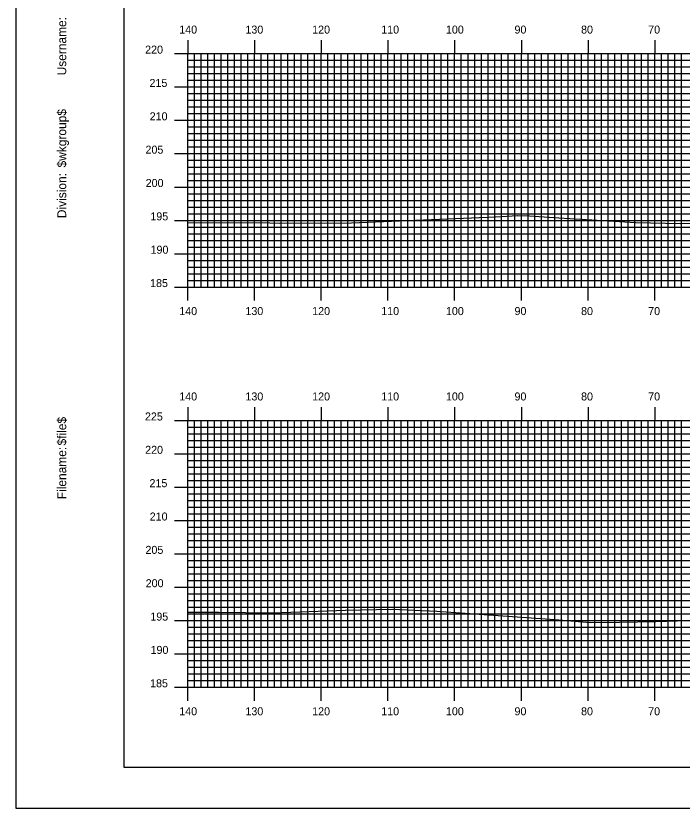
# Model space of a CAD drawing. Extents: x 1812554 to 1812897, y 442591 to 442811.
# Drawn here: x 1812554.2 to 1812654, y 442590.5 to 442709.3 of the extents above; entities that cross this region are included whole.
import ezdxf

# ---------------------------------------------------------------- set-up
doc = ezdxf.new("R2010")
doc.units = 0
for name, color, linetype in [('BORDER', 7, 'Continuous'), ('H_V ANNOTATION', 7, 'Continuous'), ('MAJOR', 7, 'Continuous'), ('MINOR', 7, 'Continuous'), ('PLOT BOUNDARY', 7, 'Continuous'), ('S_Roadway_Centerline', 7, 'Continuous')]:
    doc.layers.add(name, color=color, linetype=linetype)

msp = doc.modelspace()

# ---------------------------------------------------------------- linework, layer by layer
at = {"layer": 'BORDER'}
msp.add_lwpolyline([(1812570.34, 442596.67), (1812890.34, 442596.67), (1812890.34, 442806.67), (1812570.34, 442806.67)], close=True, dxfattribs=at)
at = {"layer": 'MAJOR'}
for p, q in [((1812579.94, 442705.67), (1812579.94, 442703.67)), ((1812589.94, 442705.67), (1812589.94, 442703.67)), ((1812599.94, 442705.67), (1812599.94, 442703.67)), ((1812609.94, 442705.67), (1812609.94, 442703.67)), ((1812619.94, 442705.67), (1812619.94, 442703.67)), ((1812629.94, 442705.67), (1812629.94, 442703.67)), ((1812639.94, 442705.67), (1812639.94, 442703.67)), ((1812649.94, 442705.67), (1812649.94, 442703.67)), ((1812577.94, 442703.67), (1812579.94, 442703.67)), ((1812579.94, 442703.67), (1812859.94, 442703.67)), ((1812579.94, 442668.67), (1812579.94, 442703.67)), ((1812579.94, 442668.67), (1812579.94, 442703.67)), ((1812579.94, 442703.67), (1812859.94, 442703.67)), ((1812589.94, 442668.67), (1812589.94, 442703.67)), ((1812599.94, 442668.67), (1812599.94, 442703.67)), ((1812609.94, 442668.67), (1812609.94, 442703.67)), ((1812619.94, 442668.67), (1812619.94, 442703.67)), ((1812629.94, 442668.67), (1812629.94, 442703.67)), ((1812639.94, 442668.67), (1812639.94, 442703.67)), ((1812649.94, 442668.67), (1812649.94, 442703.67)), ((1812577.94, 442698.67), (1812579.94, 442698.67)), ((1812579.94, 442698.67), (1812859.94, 442698.67)), ((1812577.94, 442693.67), (1812579.94, 442693.67)), ((1812579.94, 442693.67), (1812859.94, 442693.67)), ((1812577.94, 442688.67), (1812579.94, 442688.67)), ((1812579.94, 442688.67), (1812859.94, 442688.67)), ((1812577.94, 442683.67), (1812579.94, 442683.67)), ((1812579.94, 442683.67), (1812859.94, 442683.67)), ((1812577.94, 442678.67), (1812579.94, 442678.67)), ((1812579.94, 442678.67), (1812859.94, 442678.67)), ((1812577.94, 442673.67), (1812579.94, 442673.67)), ((1812579.94, 442673.67), (1812859.94, 442673.67)), ((1812577.94, 442668.67), (1812579.94, 442668.67)), ((1812579.94, 442668.67), (1812859.94, 442668.67)), ((1812579.94, 442668.67), (1812859.94, 442668.67)), ((1812579.94, 442666.66), (1812579.94, 442668.67)), ((1812589.94, 442666.66), (1812589.94, 442668.67)), ((1812599.94, 442666.66), (1812599.94, 442668.67)), ((1812609.94, 442666.66), (1812609.94, 442668.67)), ((1812619.94, 442666.66), (1812619.94, 442668.67)), ((1812629.94, 442666.66), (1812629.94, 442668.67)), ((1812639.94, 442666.66), (1812639.94, 442668.67)), ((1812649.94, 442666.66), (1812649.94, 442668.67)), ((1812579.94, 442650.67), (1812579.94, 442648.67)), ((1812589.94, 442650.67), (1812589.94, 442648.67)), ((1812599.94, 442650.67), (1812599.94, 442648.67)), ((1812609.94, 442650.67), (1812609.94, 442648.67)), ((1812619.94, 442650.67), (1812619.94, 442648.67)), ((1812629.94, 442650.67), (1812629.94, 442648.67)), ((1812639.94, 442650.67), (1812639.94, 442648.67)), ((1812649.94, 442650.67), (1812649.94, 442648.67)), ((1812577.94, 442648.67), (1812579.94, 442648.67)), ((1812579.94, 442648.67), (1812859.94, 442648.67)), ((1812579.94, 442608.67), (1812579.94, 442648.67)), ((1812579.94, 442608.67), (1812579.94, 442648.67)), ((1812579.94, 442648.67), (1812859.94, 442648.67)), ((1812589.94, 442608.67), (1812589.94, 442648.67)), ((1812599.94, 442608.67), (1812599.94, 442648.67)), ((1812609.94, 442608.67), (1812609.94, 442648.67)), ((1812619.94, 442608.67), (1812619.94, 442648.67)), ((1812629.94, 442608.67), (1812629.94, 442648.67)), ((1812639.94, 442608.67), (1812639.94, 442648.67)), ((1812649.94, 442608.67), (1812649.94, 442648.67)), ((1812577.94, 442643.67), (1812579.94, 442643.67)), ((1812579.94, 442643.67), (1812859.94, 442643.67)), ((1812577.94, 442638.67), (1812579.94, 442638.67)), ((1812579.94, 442638.67), (1812859.94, 442638.67)), ((1812577.94, 442633.67), (1812579.94, 442633.67)), ((1812579.94, 442633.67), (1812859.94, 442633.67)), ((1812577.94, 442628.67), (1812579.94, 442628.67)), ((1812579.94, 442628.67), (1812859.94, 442628.67)), ((1812577.94, 442623.67), (1812579.94, 442623.67)), ((1812579.94, 442623.67), (1812859.94, 442623.67)), ((1812577.94, 442618.67), (1812579.94, 442618.67)), ((1812579.94, 442618.67), (1812859.94, 442618.67)), ((1812577.94, 442613.67), (1812579.94, 442613.67)), ((1812579.94, 442613.67), (1812859.94, 442613.67)), ((1812577.94, 442608.67), (1812579.94, 442608.67)), ((1812579.94, 442608.67), (1812859.94, 442608.67)), ((1812579.94, 442608.67), (1812859.94, 442608.67)), ((1812579.94, 442606.66), (1812579.94, 442608.67)), ((1812589.94, 442606.66), (1812589.94, 442608.67)), ((1812599.94, 442606.66), (1812599.94, 442608.67)), ((1812609.94, 442606.66), (1812609.94, 442608.67)), ((1812619.94, 442606.66), (1812619.94, 442608.67)), ((1812629.94, 442606.66), (1812629.94, 442608.67)), ((1812639.94, 442606.66), (1812639.94, 442608.67)), ((1812649.94, 442606.66), (1812649.94, 442608.67))]:
    msp.add_line(p, q, dxfattribs=at)
at = {"layer": 'MINOR'}
for p, q in [((1812579.94, 442702.67), (1812859.94, 442702.67)), ((1812579.94, 442702.67), (1812581.95, 442702.67)), ((1812580.94, 442668.67), (1812580.94, 442703.67)), ((1812581.94, 442668.67), (1812581.94, 442703.67)), ((1812582.94, 442668.67), (1812582.94, 442703.67)), ((1812583.94, 442668.67), (1812583.94, 442703.67)), ((1812584.94, 442668.67), (1812584.94, 442703.67)), ((1812585.94, 442668.67), (1812585.94, 442703.67)), ((1812586.94, 442668.67), (1812586.94, 442703.67)), ((1812587.94, 442668.67), (1812587.94, 442703.67)), ((1812588.94, 442668.67), (1812588.94, 442703.67)), ((1812590.94, 442668.67), (1812590.94, 442703.67)), ((1812591.94, 442668.67), (1812591.94, 442703.67)), ((1812592.94, 442668.67), (1812592.94, 442703.67)), ((1812593.94, 442668.67), (1812593.94, 442703.67)), ((1812594.94, 442668.67), (1812594.94, 442703.67)), ((1812595.94, 442668.67), (1812595.94, 442703.67)), ((1812596.94, 442668.67), (1812596.94, 442703.67)), ((1812597.94, 442668.67), (1812597.94, 442703.67)), ((1812598.94, 442668.67), (1812598.94, 442703.67)), ((1812600.94, 442668.67), (1812600.94, 442703.67)), ((1812601.94, 442668.67), (1812601.94, 442703.67)), ((1812602.94, 442668.67), (1812602.94, 442703.67)), ((1812603.94, 442668.67), (1812603.94, 442703.67)), ((1812604.94, 442668.67), (1812604.94, 442703.67)), ((1812605.94, 442668.67), (1812605.94, 442703.67)), ((1812606.94, 442668.67), (1812606.94, 442703.67)), ((1812607.94, 442668.67), (1812607.94, 442703.67)), ((1812608.94, 442668.67), (1812608.94, 442703.67)), ((1812610.94, 442668.67), (1812610.94, 442703.67)), ((1812611.94, 442668.67), (1812611.94, 442703.67)), ((1812612.94, 442668.67), (1812612.94, 442703.67)), ((1812613.94, 442668.67), (1812613.94, 442703.67)), ((1812614.94, 442668.67), (1812614.94, 442703.67)), ((1812615.94, 442668.67), (1812615.94, 442703.67)), ((1812616.94, 442668.67), (1812616.94, 442703.67)), ((1812617.94, 442668.67), (1812617.94, 442703.67)), ((1812618.94, 442668.67), (1812618.94, 442703.67)), ((1812620.94, 442668.67), (1812620.94, 442703.67)), ((1812621.94, 442668.67), (1812621.94, 442703.67)), ((1812622.94, 442668.67), (1812622.94, 442703.67)), ((1812623.94, 442668.67), (1812623.94, 442703.67)), ((1812624.94, 442668.67), (1812624.94, 442703.67)), ((1812625.94, 442668.67), (1812625.94, 442703.67)), ((1812626.94, 442668.67), (1812626.94, 442703.67)), ((1812627.94, 442668.67), (1812627.94, 442703.67)), ((1812628.94, 442668.67), (1812628.94, 442703.67)), ((1812630.94, 442668.67), (1812630.94, 442703.67)), ((1812631.94, 442668.67), (1812631.94, 442703.67)), ((1812632.94, 442668.67), (1812632.94, 442703.67)), ((1812633.94, 442668.67), (1812633.94, 442703.67)), ((1812634.94, 442668.67), (1812634.94, 442703.67)), ((1812635.94, 442668.67), (1812635.94, 442703.67)), ((1812636.94, 442668.67), (1812636.94, 442703.67)), ((1812637.94, 442668.67), (1812637.94, 442703.67)), ((1812638.94, 442668.67), (1812638.94, 442703.67)), ((1812640.94, 442668.67), (1812640.94, 442703.67)), ((1812641.94, 442668.67), (1812641.94, 442703.67)), ((1812642.94, 442668.67), (1812642.94, 442703.67)), ((1812643.94, 442668.67), (1812643.94, 442703.67)), ((1812644.94, 442668.67), (1812644.94, 442703.67)), ((1812645.94, 442668.67), (1812645.94, 442703.67)), ((1812646.94, 442668.67), (1812646.94, 442703.67)), ((1812647.94, 442668.67), (1812647.94, 442703.67)), ((1812648.94, 442668.67), (1812648.94, 442703.67)), ((1812650.94, 442668.67), (1812650.94, 442703.67)), ((1812651.94, 442668.67), (1812651.94, 442703.67)), ((1812652.94, 442668.67), (1812652.94, 442703.67)), ((1812653.94, 442668.67), (1812653.94, 442703.67)), ((1812579.94, 442701.67), (1812859.94, 442701.67)), ((1812579.94, 442701.67), (1812581.95, 442701.67)), ((1812579.94, 442700.67), (1812859.94, 442700.67)), ((1812579.94, 442700.67), (1812581.95, 442700.67)), ((1812579.94, 442699.67), (1812859.94, 442699.67)), ((1812579.94, 442699.67), (1812581.95, 442699.67)), ((1812579.94, 442697.67), (1812859.94, 442697.67)), ((1812579.94, 442697.67), (1812581.95, 442697.67)), ((1812579.94, 442696.67), (1812859.94, 442696.67)), ((1812579.94, 442696.67), (1812581.95, 442696.67)), ((1812579.94, 442695.67), (1812859.94, 442695.67)), ((1812579.94, 442695.67), (1812581.95, 442695.67)), ((1812579.94, 442694.67), (1812859.94, 442694.67)), ((1812579.94, 442694.67), (1812581.95, 442694.67)), ((1812579.94, 442692.67), (1812859.94, 442692.67)), ((1812579.94, 442692.67), (1812581.95, 442692.67)), ((1812579.94, 442691.67), (1812859.94, 442691.67)), ((1812579.94, 442691.67), (1812581.95, 442691.67)), ((1812579.94, 442690.67), (1812859.94, 442690.67)), ((1812579.94, 442690.67), (1812581.95, 442690.67)), ((1812579.94, 442689.67), (1812859.94, 442689.67)), ((1812579.94, 442689.67), (1812581.95, 442689.67)), ((1812579.94, 442687.67), (1812859.94, 442687.67)), ((1812579.94, 442687.67), (1812581.95, 442687.67)), ((1812579.94, 442686.67), (1812859.94, 442686.67)), ((1812579.94, 442686.67), (1812581.95, 442686.67)), ((1812579.94, 442685.67), (1812859.94, 442685.67)), ((1812579.94, 442685.67), (1812581.95, 442685.67)), ((1812579.94, 442684.67), (1812859.94, 442684.67)), ((1812579.94, 442684.67), (1812581.95, 442684.67)), ((1812579.94, 442682.67), (1812859.94, 442682.67)), ((1812579.94, 442682.67), (1812581.95, 442682.67)), ((1812579.94, 442681.67), (1812859.94, 442681.67)), ((1812579.94, 442681.67), (1812581.95, 442681.67)), ((1812579.94, 442680.67), (1812859.94, 442680.67)), ((1812579.94, 442680.67), (1812581.95, 442680.67)), ((1812579.94, 442679.67), (1812859.94, 442679.67)), ((1812579.94, 442679.67), (1812581.95, 442679.67)), ((1812579.94, 442677.67), (1812859.94, 442677.67)), ((1812579.94, 442677.67), (1812581.95, 442677.67)), ((1812579.94, 442676.67), (1812859.94, 442676.67)), ((1812579.94, 442676.67), (1812581.95, 442676.67)), ((1812579.94, 442675.67), (1812859.94, 442675.67)), ((1812579.94, 442675.67), (1812581.95, 442675.67)), ((1812579.94, 442674.67), (1812859.94, 442674.67)), ((1812579.94, 442674.67), (1812581.95, 442674.67)), ((1812579.94, 442672.67), (1812859.94, 442672.67)), ((1812579.94, 442672.67), (1812581.95, 442672.67)), ((1812579.94, 442671.67), (1812859.94, 442671.67)), ((1812579.94, 442671.67), (1812581.95, 442671.67)), ((1812579.94, 442670.67), (1812859.94, 442670.67)), ((1812579.94, 442670.67), (1812581.95, 442670.67)), ((1812579.94, 442669.67), (1812859.94, 442669.67)), ((1812579.94, 442669.67), (1812581.95, 442669.67)), ((1812580.94, 442608.67), (1812580.94, 442648.67)), ((1812581.94, 442608.67), (1812581.94, 442648.67)), ((1812582.94, 442608.67), (1812582.94, 442648.67)), ((1812583.94, 442608.67), (1812583.94, 442648.67)), ((1812584.94, 442608.67), (1812584.94, 442648.67)), ((1812585.94, 442608.67), (1812585.94, 442648.67)), ((1812586.94, 442608.67), (1812586.94, 442648.67)), ((1812587.94, 442608.67), (1812587.94, 442648.67)), ((1812588.94, 442608.67), (1812588.94, 442648.67)), ((1812590.94, 442608.67), (1812590.94, 442648.67)), ((1812591.94, 442608.67), (1812591.94, 442648.67)), ((1812592.94, 442608.67), (1812592.94, 442648.67)), ((1812593.94, 442608.67), (1812593.94, 442648.67)), ((1812594.94, 442608.67), (1812594.94, 442648.67)), ((1812595.94, 442608.67), (1812595.94, 442648.67)), ((1812596.94, 442608.67), (1812596.94, 442648.67)), ((1812597.94, 442608.67), (1812597.94, 442648.67)), ((1812598.94, 442608.67), (1812598.94, 442648.67)), ((1812600.94, 442608.67), (1812600.94, 442648.67)), ((1812601.94, 442608.67), (1812601.94, 442648.67)), ((1812602.94, 442608.67), (1812602.94, 442648.67)), ((1812603.94, 442608.67), (1812603.94, 442648.67)), ((1812604.94, 442608.67), (1812604.94, 442648.67)), ((1812605.94, 442608.67), (1812605.94, 442648.67)), ((1812606.94, 442608.67), (1812606.94, 442648.67)), ((1812607.94, 442608.67), (1812607.94, 442648.67)), ((1812608.94, 442608.67), (1812608.94, 442648.67)), ((1812610.94, 442608.67), (1812610.94, 442648.67)), ((1812611.94, 442608.67), (1812611.94, 442648.67)), ((1812612.94, 442608.67), (1812612.94, 442648.67)), ((1812613.94, 442608.67), (1812613.94, 442648.67)), ((1812614.94, 442608.67), (1812614.94, 442648.67)), ((1812615.94, 442608.67), (1812615.94, 442648.67)), ((1812616.94, 442608.67), (1812616.94, 442648.67)), ((1812617.94, 442608.67), (1812617.94, 442648.67)), ((1812618.94, 442608.67), (1812618.94, 442648.67)), ((1812620.94, 442608.67), (1812620.94, 442648.67)), ((1812621.94, 442608.67), (1812621.94, 442648.67)), ((1812622.94, 442608.67), (1812622.94, 442648.67)), ((1812623.94, 442608.67), (1812623.94, 442648.67)), ((1812624.94, 442608.67), (1812624.94, 442648.67)), ((1812625.94, 442608.67), (1812625.94, 442648.67)), ((1812626.94, 442608.67), (1812626.94, 442648.67)), ((1812627.94, 442608.67), (1812627.94, 442648.67)), ((1812628.94, 442608.67), (1812628.94, 442648.67)), ((1812630.94, 442608.67), (1812630.94, 442648.67)), ((1812631.94, 442608.67), (1812631.94, 442648.67)), ((1812632.94, 442608.67), (1812632.94, 442648.67)), ((1812633.94, 442608.67), (1812633.94, 442648.67)), ((1812634.94, 442608.67), (1812634.94, 442648.67)), ((1812635.94, 442608.67), (1812635.94, 442648.67)), ((1812636.94, 442608.67), (1812636.94, 442648.67)), ((1812637.94, 442608.67), (1812637.94, 442648.67)), ((1812638.94, 442608.67), (1812638.94, 442648.67)), ((1812640.94, 442608.67), (1812640.94, 442648.67)), ((1812641.94, 442608.67), (1812641.94, 442648.67)), ((1812642.94, 442608.67), (1812642.94, 442648.67)), ((1812643.94, 442608.67), (1812643.94, 442648.67)), ((1812644.94, 442608.67), (1812644.94, 442648.67)), ((1812645.94, 442608.67), (1812645.94, 442648.67)), ((1812646.94, 442608.67), (1812646.94, 442648.67)), ((1812647.94, 442608.67), (1812647.94, 442648.67)), ((1812648.94, 442608.67), (1812648.94, 442648.67)), ((1812650.94, 442608.67), (1812650.94, 442648.67)), ((1812651.94, 442608.67), (1812651.94, 442648.67)), ((1812652.94, 442608.67), (1812652.94, 442648.67)), ((1812653.94, 442608.67), (1812653.94, 442648.67)), ((1812579.94, 442647.67), (1812859.94, 442647.67)), ((1812579.94, 442647.67), (1812581.95, 442647.67)), ((1812579.94, 442646.67), (1812859.94, 442646.67)), ((1812579.94, 442646.67), (1812581.95, 442646.67)), ((1812579.94, 442645.67), (1812859.94, 442645.67)), ((1812579.94, 442645.67), (1812581.95, 442645.67)), ((1812579.94, 442644.67), (1812859.94, 442644.67)), ((1812579.94, 442644.67), (1812581.95, 442644.67)), ((1812579.94, 442642.67), (1812859.94, 442642.67)), ((1812579.94, 442642.67), (1812581.95, 442642.67)), ((1812579.94, 442641.67), (1812859.94, 442641.67)), ((1812579.94, 442641.67), (1812581.95, 442641.67)), ((1812579.94, 442640.67), (1812859.94, 442640.67)), ((1812579.94, 442640.67), (1812581.95, 442640.67)), ((1812579.94, 442639.67), (1812859.94, 442639.67)), ((1812579.94, 442639.67), (1812581.95, 442639.67)), ((1812579.94, 442637.67), (1812859.94, 442637.67)), ((1812579.94, 442637.67), (1812581.95, 442637.67)), ((1812579.94, 442636.67), (1812859.94, 442636.67)), ((1812579.94, 442636.67), (1812581.95, 442636.67)), ((1812579.94, 442635.67), (1812859.94, 442635.67)), ((1812579.94, 442635.67), (1812581.95, 442635.67)), ((1812579.94, 442634.67), (1812859.94, 442634.67)), ((1812579.94, 442634.67), (1812581.95, 442634.67)), ((1812579.94, 442632.67), (1812859.94, 442632.67)), ((1812579.94, 442632.67), (1812581.95, 442632.67)), ((1812579.94, 442631.67), (1812859.94, 442631.67)), ((1812579.94, 442631.67), (1812581.95, 442631.67)), ((1812579.94, 442630.67), (1812859.94, 442630.67)), ((1812579.94, 442630.67), (1812581.95, 442630.67)), ((1812579.94, 442629.67), (1812859.94, 442629.67)), ((1812579.94, 442629.67), (1812581.95, 442629.67)), ((1812579.94, 442627.67), (1812859.94, 442627.67)), ((1812579.94, 442627.67), (1812581.95, 442627.67)), ((1812579.94, 442626.67), (1812859.94, 442626.67)), ((1812579.94, 442626.67), (1812581.95, 442626.67)), ((1812579.94, 442625.67), (1812859.94, 442625.67)), ((1812579.94, 442625.67), (1812581.95, 442625.67)), ((1812579.94, 442624.67), (1812859.94, 442624.67)), ((1812579.94, 442624.67), (1812581.95, 442624.67)), ((1812579.94, 442622.67), (1812859.94, 442622.67)), ((1812579.94, 442622.67), (1812581.95, 442622.67)), ((1812579.94, 442621.67), (1812859.94, 442621.67)), ((1812579.94, 442621.67), (1812581.95, 442621.67)), ((1812579.94, 442620.67), (1812859.94, 442620.67)), ((1812579.94, 442620.67), (1812581.95, 442620.67)), ((1812579.94, 442619.67), (1812859.94, 442619.67)), ((1812579.94, 442619.67), (1812581.95, 442619.67)), ((1812579.94, 442617.67), (1812859.94, 442617.67)), ((1812579.94, 442617.67), (1812581.95, 442617.67)), ((1812579.94, 442616.67), (1812859.94, 442616.67)), ((1812579.94, 442616.67), (1812581.95, 442616.67)), ((1812579.94, 442615.67), (1812859.94, 442615.67)), ((1812579.94, 442615.67), (1812581.95, 442615.67)), ((1812579.94, 442614.67), (1812859.94, 442614.67)), ((1812579.94, 442614.67), (1812581.95, 442614.67)), ((1812579.94, 442612.67), (1812859.94, 442612.67)), ((1812579.94, 442612.67), (1812581.95, 442612.67)), ((1812579.94, 442611.67), (1812859.94, 442611.67)), ((1812579.94, 442611.67), (1812581.95, 442611.67)), ((1812579.94, 442610.67), (1812859.94, 442610.67)), ((1812579.94, 442610.67), (1812581.95, 442610.67)), ((1812579.94, 442609.67), (1812859.94, 442609.67)), ((1812579.94, 442609.67), (1812581.95, 442609.67))]:
    msp.add_line(p, q, dxfattribs=at)
at = {"layer": 'PLOT BOUNDARY'}
msp.add_lwpolyline([(1812554.16, 442590.55), (1812894.16, 442590.55), (1812894.16, 442810.55), (1812554.16, 442810.55)], close=True, dxfattribs=at)
at = {"layer": 'S_Roadway_Centerline'}
for points in [[(1812579.94, 442678.33), (1812582.94, 442678.29), (1812590.85, 442678.35), (1812593.63, 442678.24), (1812604.49, 442678.3), (1812626.07, 442679.22), (1812629.41, 442679.42), (1812631.14, 442679.33), (1812635.57, 442679.07), (1812647.09, 442678.33), (1812653.73, 442678.2), (1812664.05, 442678.28)], [(1812579.94, 442619.93), (1812584.61, 442619.94), (1812592.63, 442619.84), (1812603.58, 442620.21), (1812610.57, 442620.39), (1812617.26, 442620.1), (1812634.97, 442618.81), (1812640.32, 442618.4), (1812644.65, 442618.45), (1812650.1, 442618.55), (1812669.43, 442619.14)]]:
    msp.add_lwpolyline(points, dxfattribs=at)

# ---------------------------------------------------------------- texts
at = {"layer": 'BORDER'}
for s, p in [('Username:', (1812561.71, 442700.4)), ('$wkgroup$', (1812561.71, 442686.6)), ('Division:', (1812561.71, 442679)), ('$file$', (1812561.71, 442644.92)), ('Filename:', (1812561.71, 442636.86))]:
    msp.add_text(s, height=1.339, rotation=90, dxfattribs=at).set_placement(p)
at = {"layer": 'H_V ANNOTATION'}
for s, p in [('140', (1812578.65, 442706.67)), ('130', (1812588.57, 442706.67)), ('120', (1812598.58, 442706.67)), ('110', (1812608.93, 442706.67)), ('100', (1812618.63, 442706.67)), ('90', (1812628.91, 442706.67)), ('80', (1812638.89, 442706.67)), ('70', (1812648.95, 442706.67)), ('220', (1812573.54, 442703.67)), ('215', (1812574.19, 442698.67)), ('210', (1812574.22, 442693.67)), ('205', (1812573.59, 442688.67)), ('200', (1812573.62, 442683.67)), ('195', (1812574.32, 442678.67)), ('190', (1812574.35, 442673.67)), ('185', (1812574.28, 442668.67)), ('140', (1812578.65, 442664.47)), ('130', (1812588.57, 442664.47)), ('120', (1812598.58, 442664.47)), ('110', (1812608.93, 442664.47)), ('100', (1812618.63, 442664.47)), ('90', (1812628.91, 442664.47)), ('80', (1812638.89, 442664.47)), ('70', (1812648.95, 442664.47)), ('140', (1812578.65, 442651.67)), ('130', (1812588.57, 442651.67)), ('120', (1812598.58, 442651.67)), ('110', (1812608.93, 442651.67)), ('100', (1812618.63, 442651.67)), ('90', (1812628.91, 442651.67)), ('80', (1812638.89, 442651.67)), ('70', (1812648.95, 442651.67)), ('225', (1812573.51, 442648.67)), ('220', (1812573.54, 442643.67)), ('215', (1812574.19, 442638.67)), ('210', (1812574.22, 442633.67)), ('205', (1812573.59, 442628.67)), ('200', (1812573.62, 442623.67)), ('195', (1812574.32, 442618.67)), ('190', (1812574.35, 442613.67)), ('185', (1812574.28, 442608.67)), ('140', (1812578.65, 442604.47)), ('130', (1812588.57, 442604.47)), ('120', (1812598.58, 442604.47)), ('110', (1812608.93, 442604.47)), ('100', (1812618.63, 442604.47)), ('90', (1812628.91, 442604.47)), ('80', (1812638.89, 442604.47)), ('70', (1812648.95, 442604.47))]:
    msp.add_text(s, height=1.2, dxfattribs=at).set_placement(p)
at = {"layer": 'MAJOR'}
for p in [(1812579.93, 442668.67), (1812579.93, 442608.67)]:
    msp.add_text('-', height=0.012, dxfattribs=at).set_placement(p)

doc.saveas('drawing.dxf')
